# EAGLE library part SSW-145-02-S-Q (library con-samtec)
THROUGH-HOLE .025" SQ POST SOCKET Source: Samtec SSW.pdf
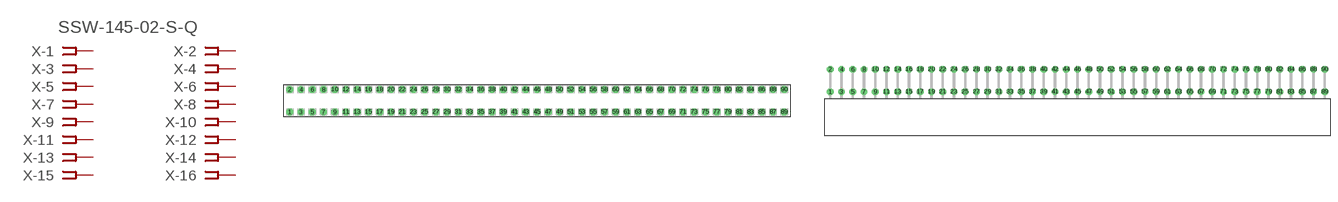
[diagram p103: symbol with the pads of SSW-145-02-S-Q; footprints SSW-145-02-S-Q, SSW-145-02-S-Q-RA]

Designator prefix X; gates -1=FPINV -2=FPIN -3=FPIN -4=FPIN -5=FPIN -6=FPIN -7=FPIN -8=FPIN -9=FPIN -10=FPIN -11=FPIN -12=FPIN -13=FPIN -14=FPIN -15=FPIN -16=FPIN -17=FPIN -18=FPIN -19=FPIN -20=FPIN -21=FPIN -22=FPIN -23=FPIN -24=FPIN -25=FPIN -26=FPIN -27=FPIN -28=FPIN -29=FPIN -30=FPIN -31=FPIN -32=FPIN -33=FPIN -34=FPIN -35=FPIN -36=FPIN -37=FPIN -38=FPIN -39=FPIN -40=FPIN -41=FPIN -42=FPIN -43=FPIN -44=FPIN -45=FPIN -46=FPIN -47=FPIN -48=FPIN -49=FPIN -50=FPIN -51=FPIN -52=FPIN -53=FPIN -54=FPIN -55=FPIN -56=FPIN -57=FPIN -58=FPIN -59=FPIN -60=FPIN -61=FPIN -62=FPIN -63=FPIN -64=FPIN -65=FPIN -66=FPIN -67=FPIN -68=FPIN -69=FPIN -70=FPIN -71=FPIN -72=FPIN -73=FPIN -74=FPIN -75=FPIN -76=FPIN -77=FPIN -78=FPIN -79=FPIN -80=FPIN -81=FPIN -82=FPIN -83=FPIN -84=FPIN -85=FPIN -86=FPIN -87=FPIN -88=FPIN -89=FPIN -90=FPIN

## SSW-145-02-S-Q (OC_FARNELL: unknown; OC_NEWARK: unknown)  [SSW-145-02-S-Q]
1  -1:1  pas
2  -2:1  pas
3  -3:1  pas
4  -4:1  pas
5  -5:1  pas
6  -6:1  pas
7  -7:1  pas
8  -8:1  pas
9  -9:1  pas
10  -10:1  pas
11  -11:1  pas
12  -12:1  pas
13  -13:1  pas
14  -14:1  pas
15  -15:1  pas
16  -16:1  pas
17  -17:1  pas
18  -18:1  pas
19  -19:1  pas
20  -20:1  pas
21  -21:1  pas
22  -22:1  pas
23  -23:1  pas
24  -24:1  pas
25  -25:1  pas
26  -26:1  pas
27  -27:1  pas
28  -28:1  pas
29  -29:1  pas
30  -30:1  pas
31  -31:1  pas
32  -32:1  pas
33  -33:1  pas
34  -34:1  pas
35  -35:1  pas
36  -36:1  pas
37  -37:1  pas
38  -38:1  pas
39  -39:1  pas
40  -40:1  pas
41  -41:1  pas
42  -42:1  pas
43  -43:1  pas
44  -44:1  pas
45  -45:1  pas
46  -46:1  pas
47  -47:1  pas
48  -48:1  pas
49  -49:1  pas
50  -50:1  pas
51  -51:1  pas
52  -52:1  pas
53  -53:1  pas
54  -54:1  pas
55  -55:1  pas
56  -56:1  pas
57  -57:1  pas
58  -58:1  pas
59  -59:1  pas
60  -60:1  pas
61  -61:1  pas
62  -62:1  pas
63  -63:1  pas
64  -64:1  pas
65  -65:1  pas
66  -66:1  pas
67  -67:1  pas
68  -68:1  pas
69  -69:1  pas
70  -70:1  pas
71  -71:1  pas
72  -72:1  pas
73  -73:1  pas
74  -74:1  pas
75  -75:1  pas
76  -76:1  pas
77  -77:1  pas
78  -78:1  pas
79  -79:1  pas
80  -80:1  pas
81  -81:1  pas
82  -82:1  pas
83  -83:1  pas
84  -84:1  pas
85  -85:1  pas
86  -86:1  pas
87  -87:1  pas
88  -88:1  pas
89  -89:1  pas
90  -90:1  pas

## SSW-145-02-S-QRA (OC_FARNELL: unknown; OC_NEWARK: unknown)  [SSW-145-02-S-Q-RA]
Pads as for SSW-145-02-S-Q

## Footprint SSW-145-02-S-Q (pad centres in mm)
THROUGH-HOLE .025" SQ POST SOCKET Source: Samtec SSW.pdf
drill 1 pad 1.5 octagon: 1 -55.88,-2.54; 2 -55.88,2.54; 3 -53.34,-2.54; 4 -53.34,2.54; 5 -50.8,-2.54; 6 -50.8,2.54; 7 -48.26,-2.54; 8 -48.26,2.54; 9 -45.72,-2.54; 10 -45.72,2.54; 11 -43.18,-2.54; 12 -43.18,2.54; 13 -40.64,-2.54; 14 -40.64,2.54; 15 -38.1,-2.54; 16 -38.1,2.54; 17 -35.56,-2.54; 18 -35.56,2.54; 19 -33.02,-2.54; 20 -33.02,2.54; 21 -30.48,-2.54; 22 -30.48,2.54; 23 -27.94,-2.54; 24 -27.94,2.54; 25 -25.4,-2.54; 26 -25.4,2.54; 27 -22.86,-2.54; 28 -22.86,2.54; 29 -20.32,-2.54; 30 -20.32,2.54; 31 -17.78,-2.54; 32 -17.78,2.54; 33 -15.24,-2.54; 34 -15.24,2.54; 35 -12.7,-2.54; 36 -12.7,2.54; 37 -10.16,-2.54; 38 -10.16,2.54; 39 -7.62,-2.54; 40 -7.62,2.54; 41 -5.08,-2.54; 42 -5.08,2.54; 43 -2.54,-2.54; 44 -2.54,2.54; 45 0,-2.54; 46 0,2.54; 47 2.54,-2.54; 48 2.54,2.54; 49 5.08,-2.54; 50 5.08,2.54; 51 7.62,-2.54; 52 7.62,2.54; 53 10.16,-2.54; 54 10.16,2.54; 55 12.7,-2.54; 56 12.7,2.54; 57 15.24,-2.54; 58 15.24,2.54; 59 17.78,-2.54; 60 17.78,2.54; 61 20.32,-2.54; 62 20.32,2.54; 63 22.86,-2.54; 64 22.86,2.54; 65 25.4,-2.54; 66 25.4,2.54; 67 27.94,-2.54; 68 27.94,2.54; 69 30.48,-2.54; 70 30.48,2.54; 71 33.02,-2.54; 72 33.02,2.54; 73 35.56,-2.54; 74 35.56,2.54; 75 38.1,-2.54; 76 38.1,2.54; 77 40.64,-2.54; 78 40.64,2.54; 79 43.18,-2.54; 80 43.18,2.54; 81 45.72,-2.54; 82 45.72,2.54; 83 48.26,-2.54; 84 48.26,2.54; 85 50.8,-2.54; 86 50.8,2.54; 87 53.34,-2.54; 88 53.34,2.54; 89 55.88,-2.54; 90 55.88,2.54

## Footprint SSW-145-02-S-Q-RA (pad centres in mm)
THROUGH-HOLE .025" SQ POST SOCKET Source: Samtec SSW.pdf
drill 1 pad 1.5 octagon: 1 -55.88,1.524; 2 -55.88,6.604; 3 -53.34,1.524; 4 -53.34,6.604; 5 -50.8,1.524; 6 -50.8,6.604; 7 -48.26,1.524; 8 -48.26,6.604; 9 -45.72,1.524; 10 -45.72,6.604; 11 -43.18,1.524; 12 -43.18,6.604; 13 -40.64,1.524; 14 -40.64,6.604; 15 -38.1,1.524; 16 -38.1,6.604; 17 -35.56,1.524; 18 -35.56,6.604; 19 -33.02,1.524; 20 -33.02,6.604; 21 -30.48,1.524; 22 -30.48,6.604; 23 -27.94,1.524; 24 -27.94,6.604; 25 -25.4,1.524; 26 -25.4,6.604; 27 -22.86,1.524; 28 -22.86,6.604; 29 -20.32,1.524; 30 -20.32,6.604; 31 -17.78,1.524; 32 -17.78,6.604; 33 -15.24,1.524; 34 -15.24,6.604; 35 -12.7,1.524; 36 -12.7,6.604; 37 -10.16,1.524; 38 -10.16,6.604; 39 -7.62,1.524; 40 -7.62,6.604; 41 -5.08,1.524; 42 -5.08,6.604; 43 -2.54,1.524; 44 -2.54,6.604; 45 0,1.524; 46 0,6.604; 47 2.54,1.524; 48 2.54,6.604; 49 5.08,1.524; 50 5.08,6.604; 51 7.62,1.524; 52 7.62,6.604; 53 10.16,1.524; 54 10.16,6.604; 55 12.7,1.524; 56 12.7,6.604; 57 15.24,1.524; 58 15.24,6.604; 59 17.78,1.524; 60 17.78,6.604; 61 20.32,1.524; 62 20.32,6.604; 63 22.86,1.524; 64 22.86,6.604; 65 25.4,1.524; 66 25.4,6.604; 67 27.94,1.524; 68 27.94,6.604; 69 30.48,1.524; 70 30.48,6.604; 71 33.02,1.524; 72 33.02,6.604; 73 35.56,1.524; 74 35.56,6.604; 75 38.1,1.524; 76 38.1,6.604; 77 40.64,1.524; 78 40.64,6.604; 79 43.18,1.524; 80 43.18,6.604; 81 45.72,1.524; 82 45.72,6.604; 83 48.26,1.524; 84 48.26,6.604; 85 50.8,1.524; 86 50.8,6.604; 87 53.34,1.524; 88 53.34,6.604; 89 55.88,1.524; 90 55.88,6.604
